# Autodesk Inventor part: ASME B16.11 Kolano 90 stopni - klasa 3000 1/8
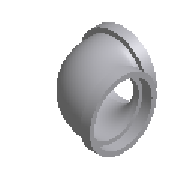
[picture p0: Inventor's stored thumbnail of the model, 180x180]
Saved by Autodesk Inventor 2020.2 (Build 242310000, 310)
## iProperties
IsCustomPart: 0
NAME: PIPING: ASME B16.11 90 Deg Elbow - Class 3000
DATA: <meta><inlinegroups number="0" deflen="0"></inlinegroups><connections number="2"></connections><angles><a>1.57079632679489</a></angles></meta>
Manager: www.cadconsulting.pl
Company: Fabian Stasiak CAD Consulting
Created: 2014-02
Part Number: ASME B16.11 Kolano 90 stopni - klasa 3000 1/8
Material: Stal
Description: Kolano 90º, kute, do przyspawania - klasa 3000
Document SubType Name: Modeling
Standard: ASME B16.11
Designer: F.Stasiak
Standard Revision: 2005
Standards Organization: ANSI
Language: pl-PL
Size Designation: 1/8
Categories: <MemberInstance><Categories><Category DisplayName="Rury cienko- i grubościenne" InternalName="4347fa0f-2144-441d-94cd-e3e15c92b736" Mnemonic="TUBEANDPIPE"><Cate
Density: 1 g/cm^3
Appearance: Płyta
Catalog Web Link: www.expertbooks.pl
Author: F.Stasiak
Subject: Zbiór ćwiczeń. Autodesk Inventor 2020. Kurs Professional
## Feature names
1. Revolve1
2. Sweep1
3. Revolve2
## Parameters: B = 10.668 mm, D = 6.0706 mm, C1 = 3.175 mm, G = 2.413 mm, J1 = 9.652 mm, A = 11.176 mm, d0 = 6.0706 mm, d1 = 10.668 mm, d2 = 3.175 mm, d3 = 9.652 mm, d4 = 0.762 mm, d5 = 2.413 mm, d23 = 90 deg, d6 = 6.0706 mm, d7 = 10.8966 mm, d8 = 10.414 mm, d9 = 10.414 mm, d10 = 5.4483 mm, d11 = 0, d12 = 6.0706 mm, d13 = 10.668 mm, d14 = 3.175 mm, d15 = 0.762 mm, d16 = 9.652 mm, d17 = 2.413 mm, d18 = 9.652 mm, d38 = 90 deg, d39 = 0, Size_Designation = 1.25 mm
